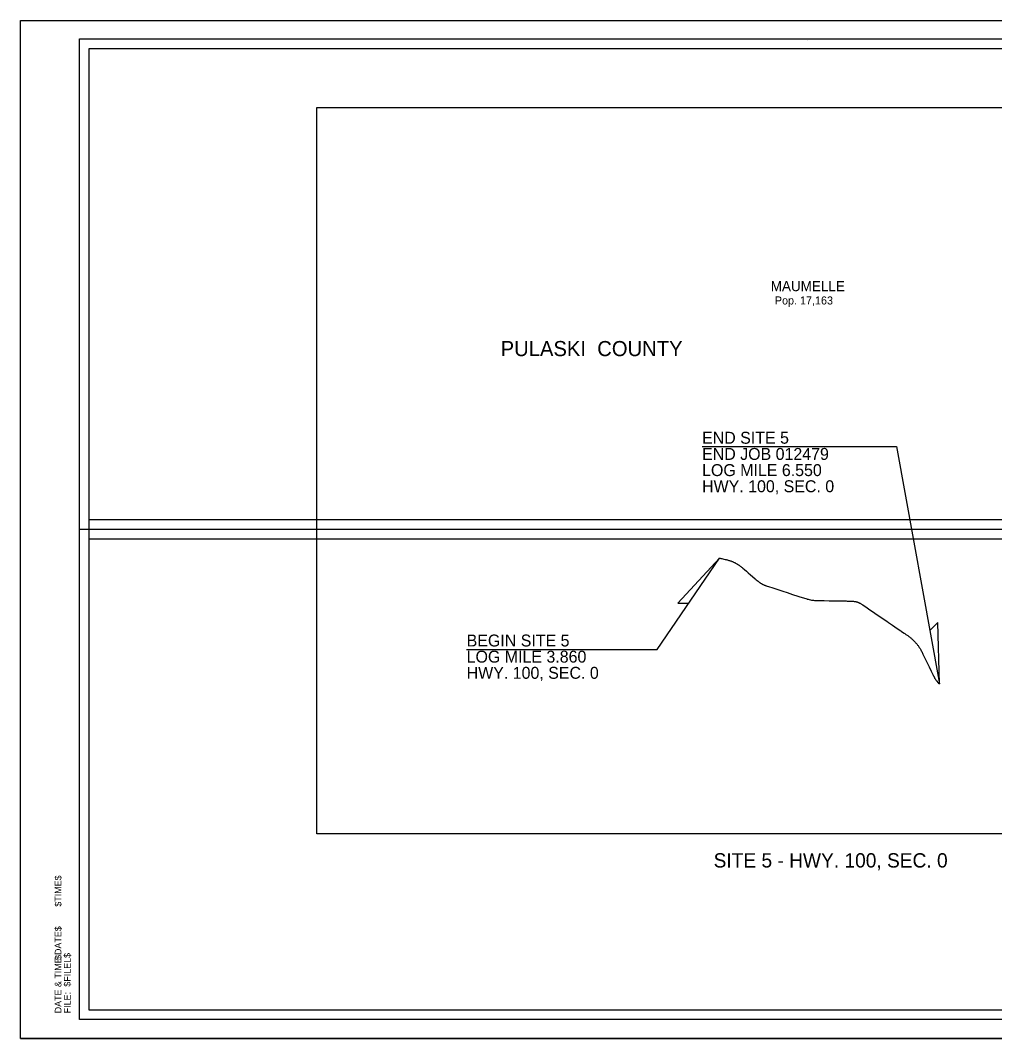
# Model space of a CAD drawing. Extents: x 10700 to 22009, y 10612 to 15552.
# Drawn here: x 17925 to 19967, y 13419 to 15552 of the extents above; entities that cross this region are included whole.
import ezdxf

# ---------------------------------------------------------------- set-up
doc = ezdxf.new("R2010")
doc.units = 0
for name, color, linetype in [('30', 7, 'Continuous'), ('6', 7, 'Continuous'), ('Default', 7, 'Continuous'), ('R_Border', 7, 'Continuous'), ('R_Border Plan-Plan', 7, 'Continuous'), ('R_Dimension', 7, 'Continuous'), ('R_No Plot', 7, 'Continuous')]:
    doc.layers.add(name, color=color, linetype=linetype)

msp = doc.modelspace()

# ---------------------------------------------------------------- linework, layer by layer
at = {"layer": 'Default'}
for points in [[(19390.6, 14425.4), (19391.5, 14425.2), (19393.4, 14424.7), (19395.3, 14424.3), (19397.5, 14423.8), (19399.7, 14423.2), (19402, 14422.7), (19404.2, 14422.2), (19405.7, 14421.8), (19407.1, 14421.5), (19408.6, 14421.1), (19410.1, 14420.6), (19411.5, 14420.2), (19413, 14419.8), (19414.1, 14419.4), (19415.3, 14418.9), (19416.4, 14418.5), (19417.6, 14418), (19418.7, 14417.5), (19419.9, 14417), (19421, 14416.5), (19422.1, 14416)], [(19422.1, 14416), (19423.7, 14415.2), (19425.2, 14414.3), (19426.7, 14413.4), (19428.2, 14412.5), (19429.8, 14411.6), (19431.2, 14410.6), (19432.5, 14409.7), (19433.8, 14408.7), (19435.2, 14407.7), (19436.4, 14406.7), (19437.7, 14405.6), (19439, 14404.6), (19442.5, 14401.4), (19446.6, 14397.9), (19450.7, 14394.5), (19455.1, 14390.6), (19459.6, 14386.7), (19465.1, 14382)], [(19465.1, 14382), (19467.1, 14380.2), (19469.2, 14378.5), (19471.4, 14376.8), (19473.5, 14375.1)], [(19473.5, 14375.1), (19474.2, 14374.6), (19474.9, 14374.1), (19475.7, 14373.6), (19476.4, 14373.1), (19477.4, 14372.5), (19478.3, 14372), (19479.3, 14371.4), (19479.9, 14371.1)], [(19479.9, 14371.1), (19480.2, 14370.9), (19481.2, 14370.4), (19482.1, 14369.9), (19483.1, 14369.5), (19484.1, 14369), (19485.1, 14368.6), (19486.1, 14368.2), (19487.1, 14367.8), (19488.1, 14367.5), (19490.4, 14366.7), (19492.7, 14366), (19501.9, 14363), (19512.6, 14359.4), (19523.3, 14356), (19531.9, 14353.2)], [(19531.9, 14353.2), (19543.3, 14349.5), (19554.7, 14345.8)], [(19554.7, 14345.8), (19558.7, 14344.5), (19566.4, 14342), (19573.4, 14339.9), (19573.9, 14339.7), (19576.2, 14339.1), (19578.4, 14338.5), (19580.7, 14338), (19583, 14337.6), (19583.6, 14337.5)], [(19583.6, 14337.5), (19584.8, 14337.3), (19587.1, 14337), (19589.1, 14336.8)], [(19589.1, 14336.8), (19589.3, 14336.8), (19591.6, 14336.6), (19593.8, 14336.5)], [(19593.8, 14336.5), (19599.7, 14336.5), (19609.5, 14336.3), (19620.3, 14336.1), (19628.3, 14336)], [(19628.3, 14336), (19636.2, 14335.9), (19647.3, 14335.7), (19655.6, 14335.6)], [(19655.6, 14335.6), (19658.2, 14335.5), (19660.8, 14335.5), (19663.4, 14335.5), (19666, 14335.4), (19667.3, 14335.4), (19668.7, 14335.3), (19670, 14335.1), (19671.3, 14335), (19672.6, 14334.8), (19673.9, 14334.6), (19674.9, 14334.4), (19675.8, 14334.2), (19676.7, 14334), (19677.6, 14333.7), (19678.5, 14333.5), (19679.4, 14333.2), (19680.3, 14332.9), (19681.1, 14332.5), (19682, 14332.2), (19682.9, 14331.8), (19683.9, 14331.3), (19685, 14330.8), (19686, 14330.3), (19687, 14329.7), (19688, 14329.1), (19689, 14328.5), (19690, 14327.9), (19690.9, 14327.3), (19691.4, 14326.9), (19696.8, 14323.3)], [(19696.8, 14323.3), (19702.9, 14319.1), (19715.9, 14310.2), (19729, 14301.2), (19741, 14293)], [(19741, 14293), (19744.5, 14290.6), (19752.6, 14285.1), (19762.8, 14278.1), (19770.1, 14273), (19771.9, 14271.8), (19777.1, 14268.3)], [(19777.1, 14268.3), (19778.5, 14267.3), (19781.1, 14265.6), (19782.4, 14264.7), (19783.6, 14263.8), (19784.9, 14263), (19786.2, 14262), (19787.4, 14261.1), (19788.6, 14260.2), (19789.9, 14259.2), (19791.1, 14258.2), (19792.3, 14257.2), (19793.6, 14256.1), (19794.8, 14255), (19796, 14253.8), (19797.2, 14252.7), (19798.4, 14251.5), (19799.5, 14250.3), (19800.7, 14249.1), (19801.4, 14248.3), (19802.1, 14247.4), (19802.9, 14246.6), (19803.6, 14245.7), (19804.5, 14244.5), (19805.5, 14243.3), (19806.4, 14242.1), (19807.3, 14240.8), (19808.2, 14239.6), (19809, 14238.3), (19809.9, 14237.1), (19810.7, 14235.8), (19811.5, 14234.5), (19812.2, 14233.1), (19813.2, 14231.4), (19814.1, 14229.7), (19815, 14228), (19815.9, 14226.3), (19816.7, 14224.5), (19817.5, 14222.8)], [(19817.5, 14222.8), (19825, 14207.3), (19829.8, 14197.4), (19833.9, 14188.8), (19837.9, 14180.5), (19838, 14180.2), (19838, 14180.1), (19838.3, 14179.5), (19838.4, 14179.4), (19838.7, 14178.7), (19838.7, 14178.7), (19839.1, 14177.9), (19839.2, 14177.8), (19839.4, 14177.3), (19839.5, 14177.2), (19839.9, 14176.5), (19839.9, 14176.4), (19840.3, 14175.8), (19840.3, 14175.7), (19840.7, 14175), (19840.7, 14175), (19841.1, 14174.2), (19841.2, 14174.2), (19841.5, 14173.5), (19841.6, 14173.4), (19841.9, 14172.9), (19842, 14172.8), (19842.4, 14172.1), (19842.4, 14172.1), (19842.8, 14171.5), (19842.9, 14171.4), (19843.6, 14170.4), (19844.3, 14169.3), (19845.1, 14168.2), (19848.5, 14164.4), (19849.1, 14163.7), (19851.2, 14161.7)]]:
    msp.add_lwpolyline(points, dxfattribs=at)
at = {"layer": 'R_Border'}
for p, q in [((18049.1, 15513.1), (21210.9, 15513.1)), ((18049.1, 13458.5), (18049.1, 15513.1)), ((19574.3, 15510.5), (19574.3, 15510.5)), ((19574.3, 15510.5), (19574.3, 15510.5)), ((18049.1, 13458.5), (18049.1, 13458.5)), ((21210.9, 13458.5), (18049.1, 13458.5))]:
    msp.add_line(p, q, dxfattribs=at)
at = {"layer": 'R_Border Plan-Plan'}
msp.add_line((18049.1, 14485.8), (21210.9, 14485.8), dxfattribs=at)
at = {"layer": 'R_Dimension'}
for p, q in [((19353.8, 14659.3), (19761.3, 14659.3)), ((18860.4, 14234.3), (19260, 14234.3))]:
    msp.add_line(p, q, dxfattribs=at)
for points in [[(19761.3, 14659.3), (19851.2, 14161.7), (19847.7, 14290.2), (19830.9, 14273.8)], [(19260, 14234.3), (19390.6, 14425.4), (19302.9, 14331.4), (19326.3, 14331.4)]]:
    msp.add_lwpolyline(points, dxfattribs=at)
at = {"layer": 'R_No Plot'}
for p, q in [((17925.1, 15552.1), (21258.5, 15552.1)), ((17925.1, 13418.7), (21258.5, 13418.7))]:
    msp.add_line(p, q, dxfattribs=at)
for points in [[(17925.1, 15552.1), (21258.5, 15552.1), (21258.5, 13418.7), (17925.1, 13418.7)], [(18069.1, 15493.1), (20564.5, 15493.1), (20564.5, 15394.3), (20739.9, 15394.3), (20980.9, 15394.3), (20980.9, 15171), (21190.9, 15171), (21190.9, 13478.5), (18069.1, 13478.5)], [(21190.9, 14505.8), (18069.1, 14505.8), (18069.1, 15493.1), (20564.5, 15493.1), (20564.5, 15394.3), (20739.9, 15394.3), (20980.9, 15394.3), (20980.9, 15171), (21190.9, 15171)], [(20713.4, 15369.5), (20713.4, 13848), (18546.7, 13848), (18546.7, 15369.5)], [(18069.1, 14465.8), (21190.9, 14465.8), (21190.9, 13478.5), (18069.1, 13478.5)]]:
    msp.add_lwpolyline(points, close=True, dxfattribs=at)

# ---------------------------------------------------------------- texts
at = {"layer": '30'}
msp.add_text('PULASKI  COUNTY', height=31.68, dxfattribs=at).set_placement((18931.6, 14848.6))
at = {"layer": '6'}
for s, height, p in [('MAUMELLE', 21.12, (19497.7, 14984.7)), ('Pop. 17,163', 16.896, (19506.3, 14956.8))]:
    msp.add_text(s, height=height, dxfattribs=at).set_placement(p)
at = {"layer": 'Default'}
for s, height, p in [('$TIME$', 13.97, (18011.1, 13695.2)), ('$DATE$', 13.97, (18011.1, 13583.5)), ('DATE & TIME:', 13.968, (18011.1, 13471.8)), ('$FILEL$', 13.97, (18030.3, 13527.6)), ('FILE: ', 13.97, (18030.3, 13471.8))]:
    msp.add_text(s, height=height, rotation=90, dxfattribs=at).set_placement(p)
at = {"layer": 'R_Dimension'}
for s, height, rotation, p in [('END SITE 5', 25, 0.0001, (19353.8, 14665.1)), ('END JOB 012479', 25, 0.0001, (19353.8, 14631.2)), ('LOG MILE 6.550', 25, 0.0001, (19353.8, 14597.3)), ('HWY. 100, SEC. 0', 25, 0.0001, (19353.8, 14563.5)), ('BEGIN SITE 5', 25, 0.0001, (18860.4, 14240.3)), ('LOG MILE 3.860', 25, 0.0001, (18860.4, 14206.5)), ('HWY. 100, SEC. 0', 25, 0.0001, (18860.4, 14172.6)), ('SITE 5 - HWY. 100, SEC. 0', 30, 359.9999, (19378, 13777.2))]:
    msp.add_text(s, height=height, rotation=rotation, dxfattribs=at).set_placement(p)

doc.saveas('drawing.dxf')
